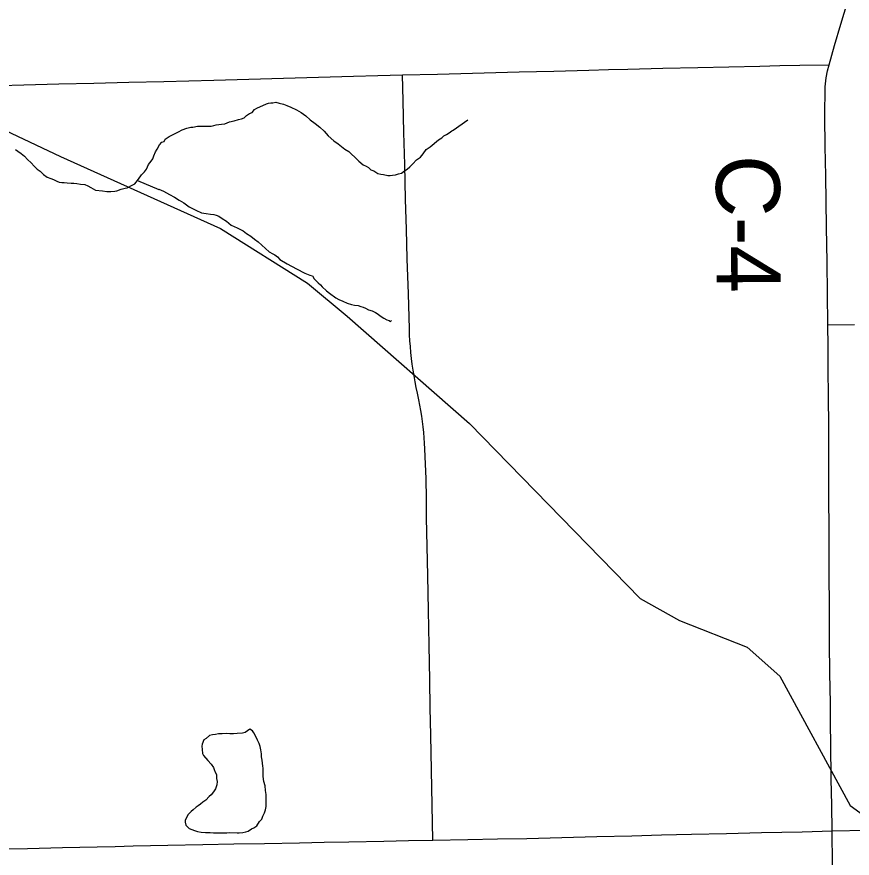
# Model space of a CAD drawing. Extents: x 103424 to 286016, y 38711 to 110967.
# Drawn here: x 130598 to 134541, y 63924 to 67894 of the extents above; entities that cross this region are included whole.
import ezdxf

# ---------------------------------------------------------------- set-up
doc = ezdxf.new("R2010")
doc.units = 0
for name, color, linetype in [('GM_X_County_Road', 7, 'Continuous'), ('GM_X_County_Road_Text', 7, 'Continuous'), ('GM_X_Minor_Lake', 7, 'Continuous'), ('GM_X_Minor_River', 7, 'Continuous'), ('GM_X_Rail_Line', 7, 'Continuous'), ('GM_X_Township_Road', 7, 'Continuous')]:
    doc.layers.add(name, color=color, linetype=linetype)

msp = doc.modelspace()

# ---------------------------------------------------------------- linework, layer by layer
at = {"layer": 'GM_X_County_Road'}
for points in [[(134446.7, 64052.2), (134444.6, 64174.1), (134442.4, 64296.1), (134440.4, 64461.2), (134439.2, 64558.1), (134438, 64655.1), (134436.3, 64797.5), (134434.6, 64939.9), (134433.9, 65104.9), (134433.2, 65270), (134432.7, 65369.1), (134432.3, 65468.3), (134431.6, 65633.4), (134430.9, 65798.4), (134430.6, 65881.9), (134430.2, 65965.3), (134429.1, 66099.9), (134428.1, 66234.3), (134427.3, 66337.6), (134426.5, 66440.8), (134424.8, 66588.7), (134423.2, 66736.6), (134420.4, 66901.6), (134418.3, 67022.6), (134416.2, 67143.6), (134414, 67282.5), (134411.8, 67421.4), (134413.9, 67563.7), (134418.4, 67606.3), (134425, 67639.7), (134432.2, 67667.9), (134444.4, 67713.5), (134458.4, 67758.3), (134487.9, 67859.2), (134535, 68017.3)], [(130518, 67570.6), (130631.1, 67573.2), (130796.1, 67577.2), (130961.2, 67581.2), (131126.2, 67585.3), (131291.2, 67589.3), (131409.2, 67592.2), (131527.3, 67595), (131692.3, 67599.6), (131857.3, 67604.1), (132022.3, 67608.6), (132187.3, 67613.2), (132302.7, 67616.3), (132418.2, 67619.5), (132583.2, 67623.6), (132693.3, 67626.4), (132803.4, 67629.1), (132968.4, 67633.6), (133133.4, 67638), (133298.4, 67642.5), (133390.2, 67645), (133482.1, 67647.4), (133647.1, 67651.3), (133812.2, 67655.1), (133958.9, 67658.5), (134105.6, 67661.9), (134199.5, 67664.1), (134293.3, 67666.4), (134432.2, 67667.9)], [(134448.5, 63892.5), (134446.7, 64052.2)]]:
    msp.add_lwpolyline(points, dxfattribs=at)
at = {"layer": 'GM_X_Minor_Lake'}
for points in [[(131698.3, 64532.8), (131676.4, 64516.3), (131662.3, 64514.1), (131638.1, 64511.6), (131619.9, 64511.4), (131603.8, 64511.1), (131585.6, 64512.8), (131567.5, 64510.5), (131549.3, 64510.2), (131535.2, 64507.9), (131521.1, 64505.7), (131507.1, 64503.4), (131491.2, 64489), (131481.2, 64482.8), (131473.4, 64462.5), (131471.6, 64452.3), (131471.9, 64436.2), (131474.2, 64418), (131478.4, 64408), (131499, 64384.1), (131515.4, 64368.2), (131525.7, 64352.2), (131529.9, 64342.2), (131534.2, 64330.1), (131540.4, 64318.1), (131540.7, 64299.9), (131543, 64285.8), (131541.3, 64269.6), (131535.5, 64251.4), (131525.6, 64237.1), (131515.8, 64222.8), (131505.8, 64214.5), (131490, 64198.1), (131476, 64187.8), (131464.1, 64179.5), (131454.1, 64171.2), (131444.1, 64165), (131430.2, 64152.7), (131420.2, 64144.4), (131404.4, 64128), (131400.5, 64117.8), (131392.7, 64103.6), (131392.8, 64093.5), (131395.1, 64079.4), (131411.5, 64063.5), (131423.7, 64059.6), (131435.9, 64053.8)], [(131698.3, 64532.8), (131676.4, 64516.3), (131662.3, 64514.1), (131638.1, 64511.6), (131619.9, 64511.4), (131603.8, 64511.1), (131585.6, 64512.8), (131567.5, 64510.5), (131549.3, 64510.2), (131535.2, 64507.9), (131521.1, 64505.7), (131507.1, 64503.4), (131491.2, 64489), (131481.2, 64482.8), (131473.4, 64462.5), (131471.6, 64452.3), (131471.9, 64436.2), (131474.2, 64418), (131478.4, 64408), (131499, 64384.1), (131515.4, 64368.2), (131525.7, 64352.2), (131529.9, 64342.2), (131534.2, 64330.1), (131540.4, 64318.1), (131540.7, 64299.9), (131543, 64285.8), (131541.3, 64269.6), (131535.5, 64251.4), (131525.6, 64237.1), (131515.8, 64222.8), (131505.8, 64214.5), (131490, 64198.1), (131476, 64187.8), (131464.1, 64179.5), (131454.1, 64171.2), (131444.1, 64165), (131430.2, 64152.7), (131420.2, 64144.4), (131404.4, 64128), (131400.5, 64117.8), (131392.7, 64103.6), (131392.8, 64093.5), (131395.1, 64079.4), (131411.5, 64063.5), (131423.7, 64059.6), (131435.9, 64053.8), (131450.1, 64050), (131468.3, 64046.2), (131488.5, 64044.5), (131510.7, 64044.9), (131526.9, 64043.1), (131545, 64043.4), (131563.2, 64043.7), (131577.3, 64044), (131589.4, 64044.1), (131603.5, 64044.4), (131637.9, 64042.9), (131648, 64043.1), (131664.1, 64045.4), (131678.2, 64047.6), (131690.2, 64051.9), (131706.2, 64062.2), (131716.2, 64066.4), (131730.1, 64076.8), (131743.9, 64097.2), (131753.8, 64107.5), (131759.6, 64121.7), (131767.4, 64138), (131771.2, 64152.2), (131775, 64168.4), (131774.7, 64186.6), (131774.4, 64204.8), (131774.1, 64225), (131771.7, 64243.1), (131769.4, 64265.3), (131763, 64285.4), (131760.5, 64309.6), (131760.3, 64325.8), (131760.1, 64337.9), (131759.9, 64348), (131759.7, 64358.1), (131757.5, 64372.2), (131755.2, 64386.3), (131752.9, 64402.4), (131752.7, 64416.5), (131750.4, 64434.7), (131746.1, 64450.8), (131741.8, 64464.9), (131733.5, 64480.9), (131725, 64500.9), (131716.7, 64515), (131710.5, 64525), (131698.3, 64532.8)], [(131435.9, 64053.8), (131450.1, 64050), (131468.3, 64046.2), (131488.5, 64044.5), (131510.7, 64044.9), (131526.9, 64043.1), (131545, 64043.4), (131563.2, 64043.7), (131577.3, 64044), (131589.4, 64044.1), (131603.5, 64044.4), (131637.9, 64042.9), (131648, 64043.1), (131664.1, 64045.4), (131678.2, 64047.6), (131690.2, 64051.9), (131706.2, 64062.2), (131716.2, 64066.4), (131730.1, 64076.8), (131743.9, 64097.2), (131753.8, 64107.5), (131759.6, 64121.7), (131767.4, 64138), (131771.2, 64152.2), (131775, 64168.4), (131774.7, 64186.6), (131774.4, 64204.8), (131774.1, 64225), (131771.7, 64243.1), (131769.4, 64265.3), (131763, 64285.4), (131760.5, 64309.6), (131760.3, 64325.8), (131760.1, 64337.9), (131759.9, 64348), (131759.7, 64358.1), (131757.5, 64372.2), (131755.2, 64386.3), (131752.9, 64402.4), (131752.7, 64416.5), (131750.4, 64434.7), (131746.1, 64450.8), (131741.8, 64464.9), (131733.5, 64480.9), (131725, 64500.9), (131716.7, 64515), (131710.5, 64525), (131698.3, 64532.8)]]:
    msp.add_lwpolyline(points, dxfattribs=at)
at = {"layer": 'GM_X_Minor_River'}
for points in [[(130591, 67268.4), (130603.2, 67260.5), (130617.6, 67248.6), (130633.9, 67236.8), (130648.3, 67220.9), (130664.7, 67205), (130679.1, 67189), (130693.5, 67175.1), (130707.8, 67165.2), (130724.2, 67149.4), (130740.5, 67137.5), (130758.8, 67131.7), (130771, 67125.9), (130787.2, 67118.1), (130797.4, 67114.2), (130809.5, 67112.4), (130821.7, 67112.6), (130835.8, 67110.8), (130854, 67109.1), (130866.1, 67109.3), (130880.3, 67107.5), (130898.5, 67103.7), (130918.7, 67102), (130932.9, 67096.2), (130947.2, 67088.4), (130969.6, 67076.6), (131001.9, 67073.1), (131022.2, 67069.4), (131042.3, 67069.7), (131060.5, 67072), (131070.5, 67072.2), (131090.6, 67080.6), (131108.7, 67084.9), (131118.7, 67087.1), (131144.7, 67101.7), (131154.7, 67105.9), (131172.5, 67128.4), (131186.3, 67148.9), (131200.2, 67163.2), (131210.1, 67175.5), (131219.8, 67197.9), (131231.7, 67212.2), (131239.5, 67224.5), (131245.3, 67238.7), (131253.1, 67257), (131261, 67269.3), (131270.7, 67289.6), (131282.6, 67302), (131292.6, 67306.2), (131298.5, 67316.4), (131316.5, 67328.8), (131336.5, 67339.2), (131348.5, 67345.5), (131360.5, 67351.7), (131378.5, 67360.1), (131400.6, 67368.5), (131418.7, 67372.9), (131428.7, 67373), (131450.9, 67377.5), (131465, 67377.7), (131477.1, 67377.9), (131487.2, 67378), (131503.3, 67378.3), (131515.4, 67378.5), (131527.5, 67380.7), (131539.5, 67385), (131563.7, 67387.4), (131579.8, 67389.7), (131601.9, 67398.1), (131624, 67402.5), (131644.1, 67408.9), (131658.1, 67413.2), (131670.2, 67417.4), (131682.1, 67427.7), (131696.1, 67438), (131708.1, 67442.3), (131720, 67456.6), (131730, 67462.8), (131776, 67483.8), (131786.1, 67486), (131796.1, 67488.2), (131806.2, 67488.3), (131820.3, 67490.6)], [(131820.3, 67490.6), (131836.5, 67486.8), (131856.8, 67481.1), (131873, 67475.3), (131891.3, 67467.5), (131917.7, 67455.8), (131940.2, 67442.1), (131962.6, 67426.2), (131983.1, 67408.4), (132005.6, 67390.6), (132028.1, 67372.8), (132048.6, 67354.9), (132067.1, 67333), (132093.7, 67309.2), (132114.2, 67295.4), (132130.5, 67281.5), (132146.9, 67269.7), (132165.2, 67257.8), (132177.6, 67245.9), (132193.9, 67232.1), (132212.4, 67212.1), (132232.9, 67196.3), (132247.1, 67188.5), (132257.3, 67182.6), (132269.6, 67172.7), (132283.8, 67166.8), (132302.2, 67155), (132316.4, 67151.2), (132328.5, 67149.4), (132348.7, 67145.7), (132360.8, 67145.9), (132370.9, 67146.1), (132385, 67148.3), (132399.1, 67152.6), (132413.1, 67156.8), (132427.1, 67167.2), (132441.1, 67175.5), (132453, 67185.8), (132466.9, 67200.2), (132484.7, 67218.6), (132502.7, 67231.1), (132516.5, 67247.4), (132530.3, 67267.9), (132548.3, 67280.3), (132588.1, 67313.3), (132604.1, 67323.6), (132614, 67331.9), (132626, 67338.1), (132638, 67346.4), (132651.9, 67356.7), (132658, 67358.9), (132727.1, 67407.6)], [(131167.3, 67121.8), (131268.2, 67079.5), (131268.1, 67081.5), (131290.5, 67071.8), (131319, 67056.1), (131341.5, 67042.3), (131363.9, 67028.5), (131386.3, 67016.8), (131410.8, 66997), (131443.4, 66981.3), (131469.8, 66969.7), (131492.1, 66966), (131512.3, 66962.3), (131528.5, 66960.5), (131538.6, 66958.7), (131550.8, 66952.8), (131567.1, 66943), (131587.5, 66929.2), (131610, 66911.3), (131638.5, 66897.7), (131667, 66884), (131681.3, 66872.1), (131701.7, 66858.3), (131720.1, 66844.5), (131736.5, 66832.6), (131789.7, 66785), (131806, 66775.1), (131816.2, 66771.3), (131828.5, 66761.4), (131838.8, 66749.4), (131873.4, 66727.8), (131918.2, 66704.3), (131956.9, 66684.7), (131981.3, 66675), (131993.4, 66671.1), (132001.7, 66657.1), (132020.2, 66639.3), (132030.5, 66629.3), (132038.7, 66619.4), (132059.2, 66601.5), (132073.5, 66589.6), (132104.1, 66567.9), (132118.4, 66560.1), (132136.7, 66552.3), (132157, 66542.5), (132177.3, 66536.8), (132191.5, 66533), (132209.7, 66531.2), (132221.9, 66527.4), (132232, 66523.5), (132244.2, 66519.7), (132258.4, 66511.9), (132274.7, 66506.1), (132291, 66498.2), (132303.2, 66490.4), (132313.4, 66482.4), (132329.7, 66472.6), (132344, 66464.8), (132356.2, 66460.9), (132362.3, 66457), (132366.3, 66461.1)]]:
    msp.add_lwpolyline(points, dxfattribs=at)
at = {"layer": 'GM_X_Rail_Line'}
msp.add_lwpolyline([(121943.9, 72984.2), (122182.1, 72897.3), (122415.6, 72812.4), (124792.9, 71078.1), (125556.8, 70456.6), (126295.9, 69834.8), (126924.8, 69218), (127230.6, 68946.2), (127450.9, 68796.9), (129668, 67771.2), (130803.4, 67235.1), (131559.6, 66894.9), (131970.7, 66637.8), (132157, 66481.8), (132734.1, 65975.1), (133539.6, 65148.6), (133726.4, 65044.7), (134046.1, 64920.1), (134199.7, 64783.1), (134531.9, 64172.6), (134681.3, 64064.6), (135221.1, 64052.1), (135711, 63354.4)], dxfattribs=at)
at = {"layer": 'GM_X_Township_Road'}
for points in [[(132562.2, 64008.7), (132558.8, 64173.7), (132555.5, 64338.8), (132552.1, 64503.8), (132549.5, 64633.6), (132546.9, 64763.3), (132543.7, 64928.4), (132540.6, 65093.4), (132537.5, 65258.4), (132534.9, 65393.9), (132532.3, 65529.4), (132531.1, 65621.5), (132529.7, 65713.6), (132525.4, 65818.9), (132524.2, 65856), (132522.7, 65881.8), (132520.9, 65907.6), (132518.7, 65933.3), (132515.9, 65959), (132512.7, 65984.6), (132509.1, 66010.2), (132504.9, 66035.7), (132500.4, 66061.1), (132495.3, 66086.5), (132488.8, 66117.6), (132482.8, 66144.8), (132477.5, 66172.2), (132472.7, 66199.6), (132468.2, 66227.1), (132464.2, 66254.7), (132460.9, 66282.3), (132457.9, 66310), (132455.4, 66337.8), (132453.4, 66365.5), (132451.9, 66393.4), (132450.9, 66421.7), (132446, 66586.7), (132441.1, 66751.7), (132437, 66892.1), (132432.8, 67032.6), (132428.6, 67197.6), (132424.8, 67347.9), (132420.9, 67498.1), (132418.2, 67619.5)], [(134426.5, 66440.8), (134552, 66442.8)], [(130509, 63967.5), (130647.5, 63970.3), (130812.6, 63974), (130977.6, 63977.8), (131061.9, 63979.7), (131146.3, 63981.6), (131311.3, 63984.8), (131476.4, 63988), (131621.8, 63990.9), (131767.3, 63993.7), (131932.4, 63996.9), (132048.6, 63999.2), (132164.8, 64001.4), (132329.8, 64004.5), (132446, 64006.6), (132562.2, 64008.7), (132727.2, 64012), (132866.6, 64014.7), (133005.9, 64017.5), (133170.9, 64021.7), (133335.9, 64025.9), (133500.9, 64030.1), (133641.6, 64033.7), (133782.4, 64037.3), (133947.4, 64041), (134112.4, 64044.7), (134209, 64046.8), (134305.6, 64049), (134446.7, 64052.2)], [(134446.7, 64052.2), (134611.7, 64056)]]:
    msp.add_lwpolyline(points, dxfattribs=at)

# ---------------------------------------------------------------- texts
at = {"layer": 'GM_X_County_Road_Text'}
msp.add_text('C-4', height=301.87, rotation=270.4581, dxfattribs=at).set_placement((133897.1, 67240.5))

doc.saveas('drawing.dxf')
